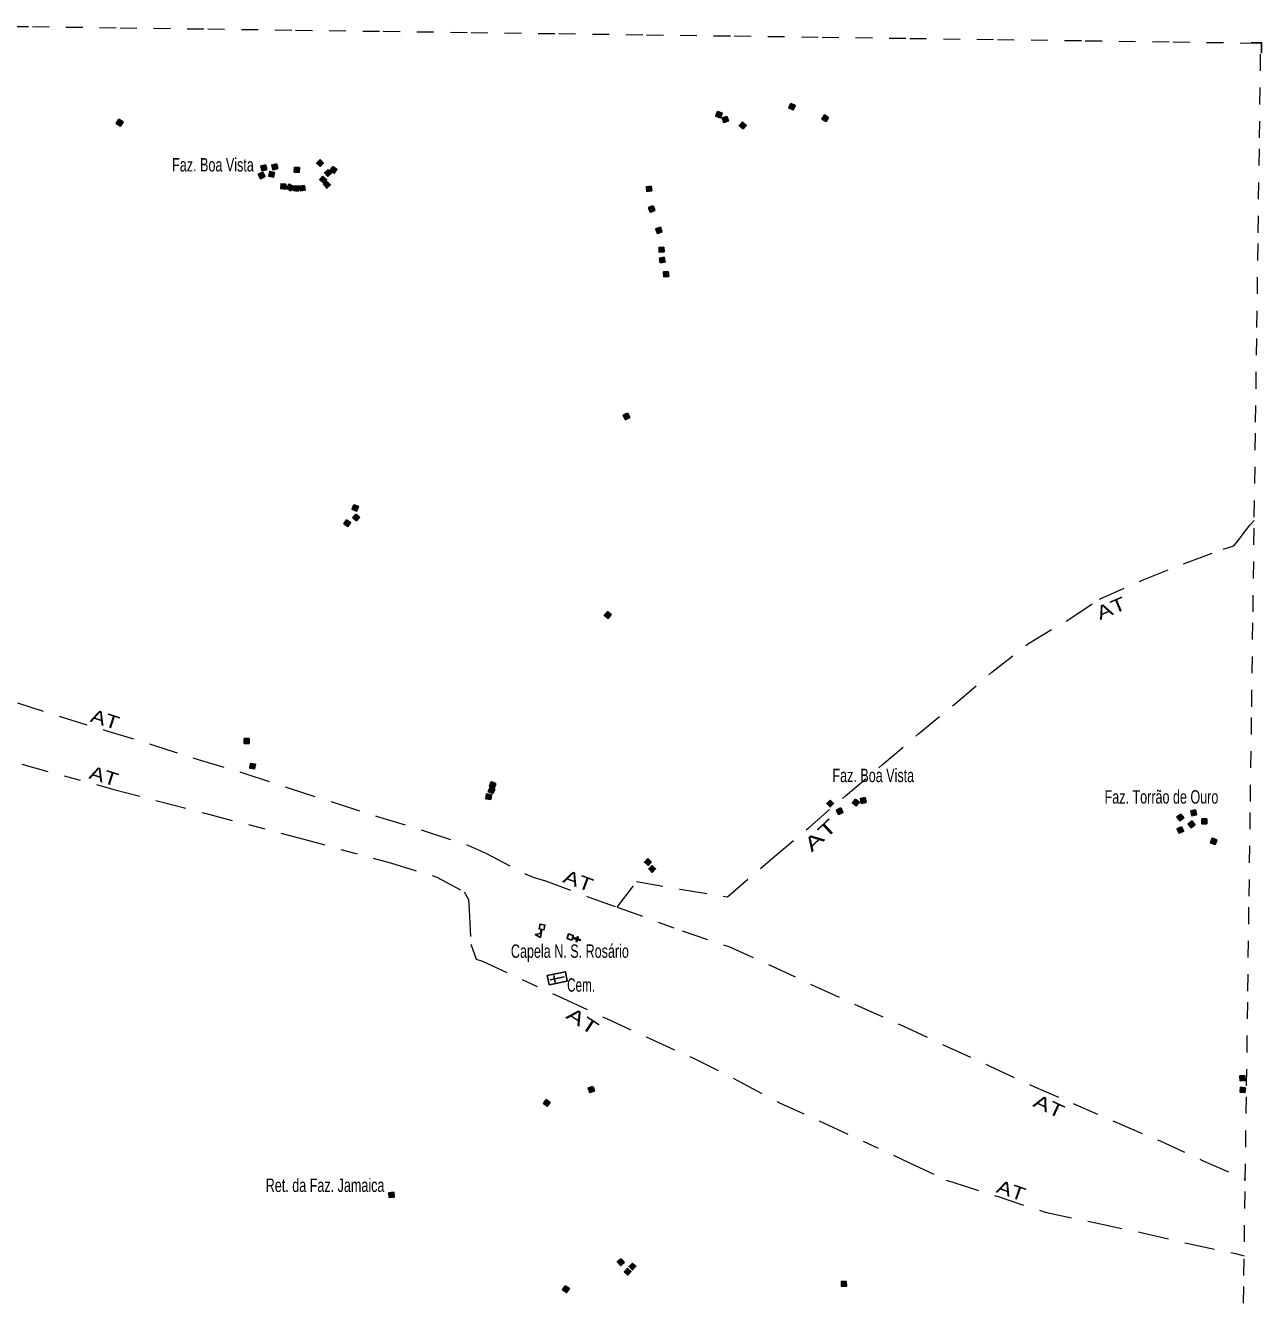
# Model space of a CAD drawing. Extents: x 679 to 705, y 7427.4 to 7455.4.
# Drawn here: x 697.64 to 705, y 7447.55 to 7455.15 of the extents above; entities that cross this region are included whole.
import ezdxf
from ezdxf.enums import TextEntityAlignment as Align

# ---------------------------------------------------------------- set-up
doc = ezdxf.new("R2010")
doc.units = 0
doc.header["$LTSCALE"] = 0.032
doc.linetypes.add('DOT_DASHED', pattern=[7.7, 5, -1.2, 0.3, -1.2])
doc.linetypes.add('SHORT_DASHED', pattern=[2.7, 1.5, -1.2])
for name, color, linetype, lineweight in [('2', 7, 'Continuous', 25), ('20', 7, 'Continuous', 25), ('4', 7, 'Continuous', 25), ('56', 7, 'DOT_DASHED', 13), ('58', 7, 'SHORT_DASHED', 13), ('6', 7, 'Continuous', 25), ('63', 7, 'Continuous', 25)]:
    doc.layers.add(name, color=color, linetype=linetype, lineweight=lineweight)
doc.layers.add('61', color=7, linetype='Continuous')

msp = doc.modelspace()

# ---------------------------------------------------------------- hatches: boundary and pattern name
at = {"layer": '2'}
for points in [[(702.1988, 7454.6887), (702.225, 7454.6762), (702.2125, 7454.65), (702.1864, 7454.6625)], [(698.1931, 7454.5944), (698.2177, 7454.5791), (698.2025, 7454.5544), (698.1778, 7454.5697)], [(701.7617, 7454.6404), (701.7891, 7454.631), (701.7797, 7454.6036), (701.7523, 7454.613)], [(701.8178, 7454.6119), (701.8273, 7454.5845), (701.7998, 7454.575), (701.7904, 7454.6024)], [(701.9105, 7454.5786), (701.9327, 7454.5599), (701.914, 7454.5378), (701.8918, 7454.5565)], [(702.4239, 7454.6054), (702.4088, 7454.5806), (702.384, 7454.5957), (702.3991, 7454.6205)], [(699.3923, 7454.3543), (699.4128, 7454.3338), (699.3923, 7454.3133), (699.3718, 7454.3338)], [(699.051, 7454.2792), (699.0636, 7454.2531), (699.0375, 7454.2405), (699.0249, 7454.2666)], [(699.0664, 7454.3232), (699.0744, 7454.2954), (699.0465, 7454.2873), (699.0385, 7454.3152)], [(699.1206, 7454.2779), (699.1148, 7454.2495), (699.0863, 7454.2553), (699.0922, 7454.2837)], [(699.1321, 7454.3295), (699.1403, 7454.3017), (699.1125, 7454.2934), (699.1043, 7454.3212)], [(699.2692, 7454.3066), (699.2671, 7454.2777), (699.2382, 7454.2798), (699.2403, 7454.3088)], [(699.4403, 7454.2946), (699.4601, 7454.2734), (699.4389, 7454.2536), (699.4191, 7454.2748)], [(699.4686, 7454.3127), (699.4929, 7454.2968), (699.477, 7454.2725), (699.4527, 7454.2884)], [(699.1891, 7454.2077), (699.1867, 7454.1788), (699.1578, 7454.1812), (699.1602, 7454.2101)], [(699.2323, 7454.1939), (699.2176, 7454.1689), (699.1926, 7454.1836), (699.2073, 7454.2086)], [(699.2655, 7454.195), (699.2625, 7454.1661), (699.2336, 7454.1692), (699.2367, 7454.1981)], [(699.2994, 7454.2001), (699.3029, 7454.1713), (699.2741, 7454.1678), (699.2706, 7454.1966)], [(699.4096, 7454.2554), (699.4314, 7454.2363), (699.4123, 7454.2145), (699.3904, 7454.2336)], [(699.4343, 7454.2246), (699.4539, 7454.2032), (699.4325, 7454.1836), (699.4129, 7454.205)], [(701.3667, 7454.1959), (701.37, 7454.1671), (701.3412, 7454.1638), (701.3379, 7454.1926)], [(701.3776, 7454.0788), (701.3878, 7454.0517), (701.3607, 7454.0415), (701.3505, 7454.0686)], [(701.4213, 7453.9509), (701.4308, 7453.9235), (701.4033, 7453.9141), (701.3939, 7453.9415)], [(701.4423, 7453.8327), (701.4438, 7453.8038), (701.4149, 7453.8022), (701.4133, 7453.8312)], [(701.4448, 7453.7722), (701.4494, 7453.7436), (701.4207, 7453.739), (701.4162, 7453.7677)], [(701.4684, 7453.6871), (701.4712, 7453.6582), (701.4423, 7453.6555), (701.4395, 7453.6843)], [(701.2256, 7452.8437), (701.2387, 7452.8179), (701.2128, 7452.8048), (701.1997, 7452.8307)], [(699.5937, 7452.2972), (699.6208, 7452.2868), (699.6104, 7452.2597), (699.5833, 7452.2701)], [(699.6064, 7452.2413), (699.6283, 7452.2222), (699.6092, 7452.2004), (699.5873, 7452.2194)], [(699.5504, 7452.208), (699.5746, 7452.1919), (699.5585, 7452.1678), (699.5344, 7452.1838)], [(701.1052, 7451.6606), (701.1279, 7451.6426), (701.1099, 7451.6199), (701.0871, 7451.6379)], [(698.9697, 7450.9031), (698.9697, 7450.8741), (698.9407, 7450.8741), (698.9407, 7450.9031)], [(699.0066, 7450.7511), (699.0025, 7450.7224), (698.9738, 7450.7265), (698.9779, 7450.7552)], [(700.4402, 7450.6355), (700.4296, 7450.6085), (700.4026, 7450.6192), (700.4132, 7450.6461)], [(700.4142, 7450.5689), (700.4095, 7450.5402), (700.3809, 7450.5449), (700.3856, 7450.5736)], [(700.4078, 7450.6138), (700.434, 7450.6014), (700.4216, 7450.5752), (700.3954, 7450.5875)], [(702.642, 7450.5512), (702.6476, 7450.5228), (702.6191, 7450.5172), (702.6135, 7450.5457)], [(702.4334, 7450.5368), (702.4539, 7450.5163), (702.4334, 7450.4958), (702.4129, 7450.5163)], [(702.4971, 7450.4896), (702.5099, 7450.4636), (702.4838, 7450.4508), (702.4711, 7450.4768)], [(702.5841, 7450.543), (702.607, 7450.5252), (702.5891, 7450.5023), (702.5663, 7450.5202)], [(704.6114, 7450.478), (704.6175, 7450.4497), (704.5891, 7450.4436), (704.583, 7450.472)], [(704.5244, 7450.4536), (704.5411, 7450.4299), (704.5174, 7450.4132), (704.5007, 7450.4369)], [(704.5908, 7450.4122), (704.6082, 7450.389), (704.585, 7450.3716), (704.5676, 7450.3948)], [(704.6784, 7450.4244), (704.6784, 7450.3954), (704.6494, 7450.3954), (704.6494, 7450.4244)], [(704.528, 7450.3777), (704.5399, 7450.3513), (704.5134, 7450.3394), (704.5015, 7450.3658)], [(704.7378, 7450.3001), (704.7289, 7450.2725), (704.7013, 7450.2814), (704.7102, 7450.309)], [(701.3457, 7450.1881), (701.3672, 7450.1686), (701.3477, 7450.1471), (701.3262, 7450.1666)], [(701.3722, 7450.1466), (701.3927, 7450.1261), (701.3721, 7450.1056), (701.3516, 7450.1261)], [(704.9048, 7448.8949), (704.9075, 7448.8661), (704.8786, 7448.8634), (704.8759, 7448.8923)], [(701.0186, 7448.8303), (701.0278, 7448.8028), (701.0003, 7448.7936), (700.9911, 7448.8211)], [(704.9087, 7448.8225), (704.9065, 7448.7936), (704.8776, 7448.7958), (704.8798, 7448.8247)], [(700.741, 7448.7522), (700.7641, 7448.7347), (700.7466, 7448.7116), (700.7235, 7448.7291)], [(699.8316, 7448.199), (699.8338, 7448.17), (699.8049, 7448.1678), (699.8027, 7448.1967)], [(701.1871, 7447.8029), (701.2053, 7447.7803), (701.1827, 7447.7621), (701.1645, 7447.7847)], [(701.2258, 7447.7466), (701.247, 7447.7268), (701.2271, 7447.7056), (701.206, 7447.7255)], [(701.2545, 7447.7774), (701.2757, 7447.7577), (701.256, 7447.7364), (701.2348, 7447.7562)], [(702.5292, 7447.6681), (702.5299, 7447.6391), (702.5009, 7447.6384), (702.5002, 7447.6674)], [(700.8545, 7447.641), (700.8785, 7447.6247), (700.8622, 7447.6007), (700.8382, 7447.617)]]:
    msp.add_hatch(color=256, dxfattribs=at).paths.add_polyline_path(points)

# ---------------------------------------------------------------- linework, layer by layer
for points in [[(702.1988, 7454.6887), (702.225, 7454.6762), (702.2125, 7454.65), (702.1864, 7454.6625)], [(698.1931, 7454.5944), (698.2177, 7454.5791), (698.2025, 7454.5544), (698.1778, 7454.5697)], [(701.7617, 7454.6404), (701.7891, 7454.631), (701.7797, 7454.6036), (701.7523, 7454.613)], [(701.8178, 7454.6119), (701.8273, 7454.5845), (701.7998, 7454.575), (701.7904, 7454.6024)], [(701.9105, 7454.5786), (701.9327, 7454.5599), (701.914, 7454.5378), (701.8918, 7454.5565)], [(702.4239, 7454.6054), (702.4088, 7454.5806), (702.384, 7454.5957), (702.3991, 7454.6205)], [(699.3923, 7454.3543), (699.4128, 7454.3338), (699.3923, 7454.3133), (699.3718, 7454.3338)], [(699.051, 7454.2792), (699.0636, 7454.2531), (699.0375, 7454.2405), (699.0249, 7454.2666)], [(699.0664, 7454.3232), (699.0744, 7454.2954), (699.0465, 7454.2873), (699.0385, 7454.3152)], [(699.1206, 7454.2779), (699.1148, 7454.2495), (699.0863, 7454.2553), (699.0922, 7454.2837)], [(699.1321, 7454.3295), (699.1403, 7454.3017), (699.1125, 7454.2934), (699.1043, 7454.3212)], [(699.2692, 7454.3066), (699.2671, 7454.2777), (699.2382, 7454.2798), (699.2403, 7454.3088)], [(699.4403, 7454.2946), (699.4601, 7454.2734), (699.4389, 7454.2536), (699.4191, 7454.2748)], [(699.4686, 7454.3127), (699.4929, 7454.2968), (699.477, 7454.2725), (699.4527, 7454.2884)], [(699.1891, 7454.2077), (699.1867, 7454.1788), (699.1578, 7454.1812), (699.1602, 7454.2101)], [(699.2323, 7454.1939), (699.2176, 7454.1689), (699.1926, 7454.1836), (699.2073, 7454.2086)], [(699.2655, 7454.195), (699.2625, 7454.1661), (699.2336, 7454.1692), (699.2367, 7454.1981)], [(699.2994, 7454.2001), (699.3029, 7454.1713), (699.2741, 7454.1678), (699.2706, 7454.1966)], [(699.4096, 7454.2554), (699.4314, 7454.2363), (699.4123, 7454.2145), (699.3904, 7454.2336)], [(699.4343, 7454.2246), (699.4539, 7454.2032), (699.4325, 7454.1836), (699.4129, 7454.205)], [(701.3667, 7454.1959), (701.37, 7454.1671), (701.3412, 7454.1638), (701.3379, 7454.1926)], [(701.3776, 7454.0788), (701.3878, 7454.0517), (701.3607, 7454.0415), (701.3505, 7454.0686)], [(701.4213, 7453.9509), (701.4308, 7453.9235), (701.4033, 7453.9141), (701.3939, 7453.9415)], [(701.4423, 7453.8327), (701.4438, 7453.8038), (701.4149, 7453.8022), (701.4133, 7453.8312)], [(701.4448, 7453.7722), (701.4494, 7453.7436), (701.4207, 7453.739), (701.4162, 7453.7677)], [(701.4684, 7453.6871), (701.4712, 7453.6582), (701.4423, 7453.6555), (701.4395, 7453.6843)], [(701.2256, 7452.8437), (701.2387, 7452.8179), (701.2128, 7452.8048), (701.1997, 7452.8307)], [(699.5937, 7452.2972), (699.6208, 7452.2868), (699.6104, 7452.2597), (699.5833, 7452.2701)], [(699.6064, 7452.2413), (699.6283, 7452.2222), (699.6092, 7452.2004), (699.5873, 7452.2194)], [(699.5504, 7452.208), (699.5746, 7452.1919), (699.5585, 7452.1678), (699.5344, 7452.1838)], [(701.1052, 7451.6606), (701.1279, 7451.6426), (701.1099, 7451.6199), (701.0871, 7451.6379)], [(698.9697, 7450.9031), (698.9697, 7450.8741), (698.9407, 7450.8741), (698.9407, 7450.9031)], [(699.0066, 7450.7511), (699.0025, 7450.7224), (698.9738, 7450.7265), (698.9779, 7450.7552)], [(700.4402, 7450.6355), (700.4296, 7450.6085), (700.4026, 7450.6192), (700.4132, 7450.6461)], [(700.4142, 7450.5689), (700.4095, 7450.5402), (700.3809, 7450.5449), (700.3856, 7450.5736)], [(700.4078, 7450.6138), (700.434, 7450.6014), (700.4216, 7450.5752), (700.3954, 7450.5875)], [(702.642, 7450.5512), (702.6476, 7450.5228), (702.6191, 7450.5172), (702.6135, 7450.5457)], [(702.4334, 7450.5368), (702.4539, 7450.5163), (702.4334, 7450.4958), (702.4129, 7450.5163)], [(702.4971, 7450.4896), (702.5099, 7450.4636), (702.4838, 7450.4508), (702.4711, 7450.4768)], [(702.5841, 7450.543), (702.607, 7450.5252), (702.5891, 7450.5023), (702.5663, 7450.5202)], [(704.6114, 7450.478), (704.6175, 7450.4497), (704.5891, 7450.4436), (704.583, 7450.472)], [(704.5244, 7450.4536), (704.5411, 7450.4299), (704.5174, 7450.4132), (704.5007, 7450.4369)], [(704.5908, 7450.4122), (704.6082, 7450.389), (704.585, 7450.3716), (704.5676, 7450.3948)], [(704.6784, 7450.4244), (704.6784, 7450.3954), (704.6494, 7450.3954), (704.6494, 7450.4244)], [(704.528, 7450.3777), (704.5399, 7450.3513), (704.5134, 7450.3394), (704.5015, 7450.3658)], [(704.7378, 7450.3001), (704.7289, 7450.2725), (704.7013, 7450.2814), (704.7102, 7450.309)], [(701.3457, 7450.1881), (701.3672, 7450.1686), (701.3477, 7450.1471), (701.3262, 7450.1666)], [(701.3722, 7450.1466), (701.3927, 7450.1261), (701.3721, 7450.1056), (701.3516, 7450.1261)], [(704.9048, 7448.8949), (704.9075, 7448.8661), (704.8786, 7448.8634), (704.8759, 7448.8923)], [(701.0186, 7448.8303), (701.0278, 7448.8028), (701.0003, 7448.7936), (700.9911, 7448.8211)], [(704.9087, 7448.8225), (704.9065, 7448.7936), (704.8776, 7448.7958), (704.8798, 7448.8247)], [(700.741, 7448.7522), (700.7641, 7448.7347), (700.7466, 7448.7116), (700.7235, 7448.7291)], [(699.8316, 7448.199), (699.8338, 7448.17), (699.8049, 7448.1678), (699.8027, 7448.1967)], [(701.1871, 7447.8029), (701.2053, 7447.7803), (701.1827, 7447.7621), (701.1645, 7447.7847)], [(701.2258, 7447.7466), (701.247, 7447.7268), (701.2271, 7447.7056), (701.206, 7447.7255)], [(701.2545, 7447.7774), (701.2757, 7447.7577), (701.256, 7447.7364), (701.2348, 7447.7562)], [(702.5292, 7447.6681), (702.5299, 7447.6391), (702.5009, 7447.6384), (702.5002, 7447.6674)], [(700.8545, 7447.641), (700.8785, 7447.6247), (700.8622, 7447.6007), (700.8382, 7447.617)]]:
    msp.add_lwpolyline(points, close=True, dxfattribs=at)
at = {"layer": '20'}
for p, q in [((700.7945, 7449.45), (700.7858, 7449.4918)), ((700.8468, 7449.483), (700.7649, 7449.4659))]:
    msp.add_line(p, q, dxfattribs=at)
msp.add_lwpolyline([(700.7583, 7449.4352), (700.7467, 7449.4909), (700.8547, 7449.5134), (700.8663, 7449.4577)], close=True, dxfattribs=at)
at = {"layer": '4'}
for points in [[(700.7105, 7449.7665), (700.6986, 7449.7687), (700.704, 7449.7972), (700.7325, 7449.7918), (700.7272, 7449.7633), (700.7154, 7449.7656)], [(700.7154, 7449.7656), (700.7064, 7449.718), (700.6753, 7449.7356), (700.7057, 7449.7408), (700.7105, 7449.7665)]]:
    msp.add_lwpolyline(points, dxfattribs=at)
at = {"layer": '56'}
for points in [[(701.1636, 7449.8989), (701.279, 7450.0513), (701.5396, 7450.0056), (701.8209, 7449.9599), (702.0914, 7450.1934), (702.3093, 7450.3757), (702.5251, 7450.562), (702.7463, 7450.7489), (702.9621, 7450.9335), (703.1822, 7451.114), (703.3963, 7451.2982), (703.6163, 7451.4707), (703.8626, 7451.6176), (704.0392, 7451.7347), (704.2989, 7451.8494), (704.5616, 7451.953), (704.7773, 7452.0328), (704.8402, 7452.0523), (704.8739, 7452.0945), (704.8964, 7452.1233), (704.936, 7452.175), (704.9618, 7452.2034)], [(697.5893, 7451.1173), (697.8488, 7451.0324), (698.1267, 7450.9482), (698.3873, 7450.868), (698.6649, 7450.7789), (698.9376, 7450.6972), (699.2088, 7450.6069), (699.4759, 7450.5217), (699.7472, 7450.4357), (700.0188, 7450.3518), (700.2741, 7450.2687), (700.3812, 7450.2199), (700.6324, 7450.0882), (700.6685, 7450.0755), (700.7364, 7450.055), (701.0013, 7449.9563), (701.1636, 7449.8989), (701.5504, 7449.7578), (701.8294, 7449.6633), (702.0802, 7449.5508), (702.3423, 7449.4277), (702.6006, 7449.3095), (702.8669, 7449.1907), (703.1253, 7449.0702), (703.3852, 7448.9513), (703.6483, 7448.8293), (703.8814, 7448.729), (704.1462, 7448.6122), (704.4008, 7448.5047), (704.6615, 7448.3847), (704.9081, 7448.2755)], [(697.6154, 7450.7502), (698.1624, 7450.6006), (698.4375, 7450.5276), (698.7141, 7450.4561), (699.2661, 7450.3116), (699.8122, 7450.1617), (700.0888, 7450.0781), (700.2508, 7449.989), (700.2782, 7449.9449), (700.2812, 7449.8826), (700.2903, 7449.6773), (700.3238, 7449.5891), (700.3603, 7449.5769), (700.8399, 7449.3557), (701.0998, 7449.234), (701.3589, 7449.1147), (701.6218, 7448.9961), (701.8858, 7448.8638), (702.1306, 7448.7323), (702.3936, 7448.6137), (702.9072, 7448.3749), (703.1251, 7448.2721), (703.1646, 7448.2584), (703.4351, 7448.1733), (703.7155, 7448.0805), (704.0164, 7448.0166), (704.2954, 7447.9573), (704.5675, 7447.8935), (704.8505, 7447.8334), (704.9019, 7447.82)]]:
    msp.add_lwpolyline(points, dxfattribs=at)
at = {"layer": '58'}
for points in [[(697.1541, 7455.1535), (697.6772, 7455.1467), (698.2003, 7455.1398), (698.7234, 7455.1329), (699.2465, 7455.1259), (699.7696, 7455.119), (700.2927, 7455.112), (700.8158, 7455.105), (701.3389, 7455.098), (701.862, 7455.091), (702.3851, 7455.084), (702.9082, 7455.0769), (703.4313, 7455.0698), (703.9544, 7455.0628), (704.4775, 7455.0556), (705.0006, 7455.0485)], [(704.8925, 7447.1379), (704.9003, 7447.7029), (704.908, 7448.268), (704.9157, 7448.833), (704.9235, 7449.3981), (704.9312, 7449.9631), (704.9389, 7450.5281), (704.9466, 7451.0932), (704.9543, 7451.6582), (704.9621, 7452.2233), (704.9698, 7452.7883), (704.9775, 7453.3534), (704.9852, 7453.9184), (704.9929, 7454.4835), (705.0006, 7455.0485)]]:
    msp.add_lwpolyline(points, dxfattribs=at)
at = {"layer": '6'}
for points in [[(700.8965, 7449.7141), (700.8929, 7449.7026), (700.8652, 7449.7112), (700.8739, 7449.7389), (700.9016, 7449.7303), (700.898, 7449.7187)], [(700.898, 7449.7187), (700.9238, 7449.7107), (700.9274, 7449.7222), (700.9321, 7449.7208), (700.9285, 7449.7092), (700.9442, 7449.7043), (700.9427, 7449.6997), (700.9271, 7449.7046), (700.9235, 7449.6931), (700.9188, 7449.6945), (700.9224, 7449.7061), (700.8965, 7449.7141)]]:
    msp.add_lwpolyline(points, dxfattribs=at)
at = {"layer": '63'}
msp.add_lwpolyline([(705.0049, 7454.9887), (705.0049, 7455.0503), (704.9442, 7455.0503)], dxfattribs=at)

# ---------------------------------------------------------------- texts
at = {"layer": '61'}
for s, width, p in [('Faz. Boa Vista', 0.7, (698.5105, 7454.2833)), ('Faz. Boa Vista', 0.7, (702.447, 7450.6436)), ('Faz. Torrão de Ouro', 0.7, (704.0693, 7450.5157)), ('Capela N. S. Rosário', 0.7, (700.5301, 7449.5965)), ('Cem.', 0.65, (700.8654, 7449.3945)), ('Ret. da Faz. Jamaica', 0.7, (699.0685, 7448.2008))]:
    msp.add_text(s, height=0.08, dxfattribs=dict(at, width=width)).set_placement(p)
for rotation, width, p in [(22.652, 1.3, (704.1236, 7451.6432)), (342.322, 1.25, (698.0982, 7450.9795)), (342.671, 1.25, (698.0911, 7450.6415)), (43.106, 1.6, (702.4026, 7450.2976)), (339.565, 1.3, (700.9178, 7450.0181)), (326.535, 1.45, (700.9349, 7449.1863)), (335.065, 1.35, (703.7206, 7448.6753)), (340.881, 1.25, (703.499, 7448.1722))]:
    msp.add_text('AT', height=0.08, rotation=rotation, dxfattribs=dict(at, width=width)).set_placement(p, align=Align.CENTER)

doc.saveas('drawing.dxf')
